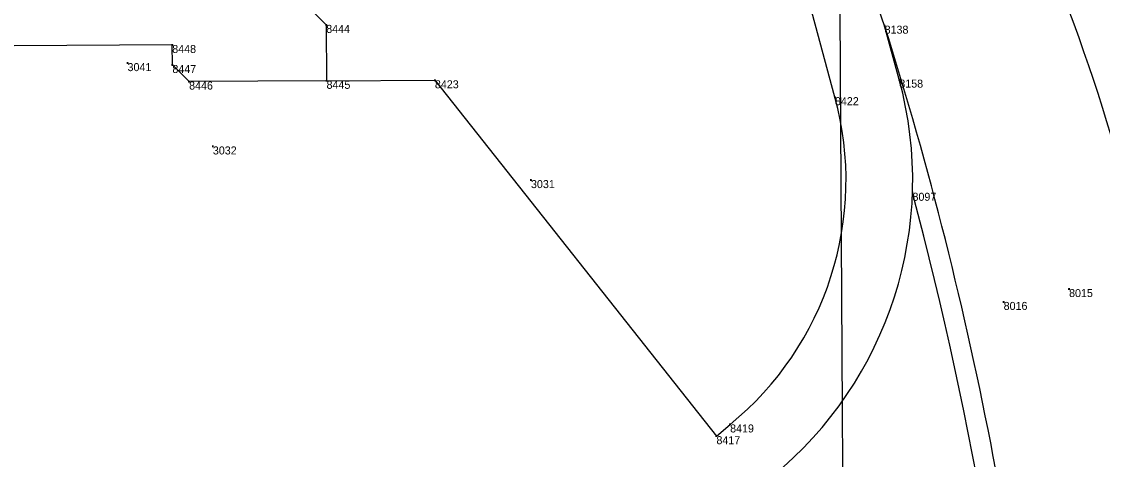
# Model space of a CAD drawing. Extents: x 2145146 to 2158053, y 137507 to 150829.
# Drawn here: x 2152334 to 2153955, y 143793 to 144448 of the extents above; entities that cross this region are included whole.
import ezdxf

# ---------------------------------------------------------------- set-up
doc = ezdxf.new("R2010")
doc.units = 0
for name, color, linetype in [('ALIGN_Cogo Points', 7, 'Continuous'), ('ALIGN_ROW Line', 7, 'Continuous'), ('PLSS_Easement', 7, 'Continuous'), ('PLSS_Property Line', 7, 'Continuous'), ('PLSS_Section Line', 7, 'Continuous')]:
    doc.layers.add(name, color=color, linetype=linetype)

msp = doc.modelspace()

# ---------------------------------------------------------------- linework, layer by layer
at = {"layer": 'ALIGN_Cogo Points'}
for points in [[(2152790.9, 144443.5), (2152790.9, 144444.7), (2152790.9, 144443.5), (2152789.7, 144443.5), (2152790.9, 144443.5), (2152790.9, 144442.3), (2152790.9, 144443.5), (2152792.1, 144443.5)], [(2153628.3, 144442.3), (2153628.3, 144443.5), (2153628.3, 144442.3), (2153627.1, 144442.3), (2153628.3, 144442.3), (2153628.3, 144441.1), (2153628.3, 144442.3), (2153629.5, 144442.3)], [(2152560, 144413.4), (2152560, 144414.6), (2152560, 144413.4), (2152558.8, 144413.4), (2152560, 144413.4), (2152560, 144412.2), (2152560, 144413.4), (2152561.2, 144413.4)], [(2152493, 144386.2), (2152493, 144387.4), (2152493, 144386.2), (2152491.8, 144386.2), (2152493, 144386.2), (2152493, 144385), (2152493, 144386.2), (2152494.2, 144386.2)], [(2152560.2, 144383.4), (2152560.2, 144384.6), (2152560.2, 144383.4), (2152559, 144383.4), (2152560.2, 144383.4), (2152560.2, 144382.2), (2152560.2, 144383.4), (2152561.4, 144383.4)], [(2152585.3, 144358.6), (2152585.3, 144359.8), (2152585.3, 144358.6), (2152584.1, 144358.6), (2152585.3, 144358.6), (2152585.3, 144357.4), (2152585.3, 144358.6), (2152586.5, 144358.6)], [(2152791.4, 144359.7), (2152791.4, 144360.9), (2152791.4, 144359.7), (2152790.2, 144359.7), (2152791.4, 144359.7), (2152791.4, 144358.5), (2152791.4, 144359.7), (2152792.6, 144359.7)], [(2152953.9, 144360.5), (2152953.9, 144361.7), (2152953.9, 144360.5), (2152952.7, 144360.5), (2152953.9, 144360.5), (2152953.9, 144359.3), (2152953.9, 144360.5), (2152955.1, 144360.5)], [(2153650.3, 144361.5), (2153650.3, 144362.7), (2153650.3, 144361.5), (2153649.1, 144361.5), (2153650.3, 144361.5), (2153650.3, 144360.3), (2153650.3, 144361.5), (2153651.5, 144361.5)], [(2153553.8, 144335.2), (2153553.8, 144336.4), (2153553.8, 144335.2), (2153552.6, 144335.2), (2153553.8, 144335.2), (2153553.8, 144334), (2153553.8, 144335.2), (2153555, 144335.2)], [(2152620.9, 144261.4), (2152620.9, 144262.6), (2152620.9, 144261.4), (2152619.7, 144261.4), (2152620.9, 144261.4), (2152620.9, 144260.2), (2152620.9, 144261.4), (2152622.1, 144261.4)], [(2153098, 144211), (2153098, 144212.2), (2153098, 144211), (2153096.8, 144211), (2153098, 144211), (2153098, 144209.8), (2153098, 144211), (2153099.2, 144211)], [(2153670.1, 144192), (2153670.1, 144193.2), (2153670.1, 144192), (2153668.9, 144192), (2153670.1, 144192), (2153670.1, 144190.8), (2153670.1, 144192), (2153671.3, 144192)], [(2153904.9, 144047.8), (2153904.9, 144049), (2153904.9, 144047.8), (2153903.7, 144047.8), (2153904.9, 144047.8), (2153904.9, 144046.6), (2153904.9, 144047.8), (2153906.1, 144047.8)], [(2153806.8, 144028.5), (2153806.8, 144029.7), (2153806.8, 144028.5), (2153805.6, 144028.5), (2153806.8, 144028.5), (2153806.8, 144027.3), (2153806.8, 144028.5), (2153808, 144028.5)], [(2153396.6, 143845), (2153396.6, 143846.2), (2153396.6, 143845), (2153395.4, 143845), (2153396.6, 143845), (2153396.6, 143843.8), (2153396.6, 143845), (2153397.8, 143845)], [(2153376.1, 143827.4), (2153376.1, 143828.6), (2153376.1, 143827.4), (2153374.9, 143827.4), (2153376.1, 143827.4), (2153376.1, 143826.2), (2153376.1, 143827.4), (2153377.3, 143827.4)]]:
    msp.add_lwpolyline(points, dxfattribs=at)
at = {"layer": 'ALIGN_ROW Line'}
for points in [[(2153628.3, 144442.3), (2153560.6, 144636.3)], [(2153650.3, 144361.5), (2153650.3, 144361.5), (2153628.3, 144442.3)]]:
    msp.add_lwpolyline(points, dxfattribs=at)
for centre, radius, start, end in [((2151128.8, 143423.6), 2964.9, 12.8977, 26.5388), ((2148261, 142743.9), 5629.6, 4, 17.5591), ((2153098, 144211), 572.4, 309.2008, 15.2408)]:
    msp.add_arc(centre, radius, start, end, dxfattribs=at)
at = {"layer": 'PLSS_Easement'}
msp.add_arc((2148261, 142743.9), 5599.6, 4, 14.9874, dxfattribs=at)
at = {"layer": 'PLSS_Property Line'}
for points in [[(2152870.9, 145699), (2152870.9, 145699), (2152531.6, 145796.4), (2152448.8, 145508), (2152450.5, 145181.5), (2152296.2, 145180.7), (2152297.7, 144904.8), (2152369, 144834.2), (2152763.9, 144836.2), (2152765.8, 144468.4), (2152790.9, 144443.5), (2152791.4, 144359.7), (2152585.3, 144358.6), (2152560.2, 144383.4), (2152560, 144413.4), (2152243.4, 144411.8), (2152211, 144379), (2152211.5, 144277.6), (2152191.7, 144277.5), (2152193.9, 143760.5), (2152292.1, 143739.4), (2152358.2, 143726.6)], [(2153553.8, 144335.2), (2153553.8, 144335.2), (2153468.6, 144650.7), (2153468.6, 144650.7)], [(2152791.4, 144359.7), (2152953.9, 144360.5), (2153376.1, 143827.4), (2153396.6, 143845), (2153396.6, 143845)]]:
    msp.add_lwpolyline(points, dxfattribs=at)
msp.add_arc((2153098, 144211), 472.4, 309.2008, 15.2408, dxfattribs=at)
at = {"layer": 'PLSS_Section Line'}
msp.add_lwpolyline([(2153570, 143016.2), (2153554.7, 145654.3)], dxfattribs=at)

# ---------------------------------------------------------------- texts
at = {"layer": 'ALIGN_Cogo Points'}
for s, p in [('8444', (2152790.9, 144431.5)), ('8138', (2153628.3, 144430.3)), ('8448', (2152560, 144401.4)), ('3041', (2152493, 144374.2)), ('8447', (2152560.2, 144371.4)), ('8446', (2152585.3, 144346.6)), ('8445', (2152791.4, 144347.7)), ('8423', (2152953.9, 144348.5)), ('8158', (2153650.3, 144349.5)), ('8422', (2153553.8, 144323.2)), ('3032', (2152620.9, 144249.4)), ('3031', (2153098, 144199)), ('8097', (2153670.1, 144180)), ('8015', (2153904.9, 144035.8)), ('8016', (2153806.8, 144016.5)), ('8419', (2153396.6, 143833)), ('8417', (2153376.1, 143815.4))]:
    msp.add_text(s, height=12, dxfattribs=at).set_placement(p)

doc.saveas('drawing.dxf')
